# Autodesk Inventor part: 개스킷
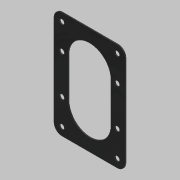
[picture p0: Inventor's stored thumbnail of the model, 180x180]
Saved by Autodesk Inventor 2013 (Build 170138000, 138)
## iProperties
Created: 2019-03
Part Number: 개스킷
Material: 고무
Document SubType Name: Modeling
Designer: mduedu
Density: 1 g/cm^3
Author: mduedu
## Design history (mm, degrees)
sketch "스케치1"
  geometry: L1 (-60, 40)-(60, 40); L2 (60, 40)-(60, -40); L3 (60, -40)-(-60, -40); L4 (-60, -40)-(-60, 40); L5 (-60, 40)-(60, -40); L6 (60, 40)-(-60, -40); 1 further point
  constraints: 12 end point, 2 midpoint, 2 parallel, 1 horizontal, 1 perpendicular
  dimensions: "d21" = 120 distance of L2.end L3.end; "d22" = 80 distance of L1.end L2.end
extrude "돌출1" new body sketch "스케치1" distance "d3" = 1; taper "d4" = 0 deg
fillet "모깎기1" dims "d5" = 9
sketch "스케치2" dims "d6" = 48
  geometry: L1 (-24, -22)-(24, -22); L2 (24, -22)-(24, 22); L3 (24, 22)-(-24, 22); L4 (-24, 22)-(-24, -22); L5 (-24, -22)-(24, 22); L6 (24, -22)-(-24, 22); 3 further points
  constraints: 12 end point, 4 midpoint, 2 horizontal alignment, 2 parallel, 1 horizontal, 1 perpendicular, 4 other
  dimensions: "d8" = 22 distance from line of L3 point (0, 0)
extrude "돌출2" cut sketch "스케치2" stored distance "d9" = 1; taper "d10" = 0 deg
sketch "스케치3"
  geometry: L1 (-24, -22)-(-24, 22) reference; L2 (24, 22)-(24, -22) reference; L3 (40, -51)-(40, 51) reference; L4 (31, 60)-(-31, 60) reference; L5 (-40, 51)-(-40, -51) reference; L6 (-31, -60)-(31, -60) reference; L7 (-31, 51)-(31, 51); L8 (31, 51)-(31, -51); L9 (31, -51)-(-31, -51); L10 (-31, -51)-(-31, 51); A1 r 24 centre (0, 22) between (24, 22) and (-24, 22) reference; A2 r 24 centre (0, -22) between (-24, -22) and (24, -22) reference; A3 r 9 centre (31, -51) between (31, -60) and (40, -51) reference; A4 r 9 centre (31, 51) between (40, 51) and (31, 60) reference; A5 r 9 centre (-31, 51) between (-31, 60) and (-40, 51) reference; A6 r 9 centre (-31, -51) between (-40, -51) and (-31, -60) reference; 9 further points
  constraints: 8 end point, 4 coincident, 4 horizontal alignment, 4 point on line, 2 parallel, 1 horizontal, 1 perpendicular
  dimensions: "d23" = 102 distance between parallel lines of L9 L7 (derived); "d24" = 29 distance from line of point (-31, 22) L7 (derived); "d25" = 29 distance from line of point (-31, -22) L9 (derived)
hole "구멍1" sketch "스케치3" at (-31, 51), (31, 51), (31, -51), (-31, -51), (-31, -22), (-31, 22), (31, 22), (31, -22) diameter "d14" = 5.5; stored, may be unused: countersink angle "d18" = 90 deg, drill point angle "d20" = 118 deg; dims "d15" = 6, "d16" = 4, "d17" = 2, "d19" = 8
node "솔리드1"
node "투영된 루프1"
